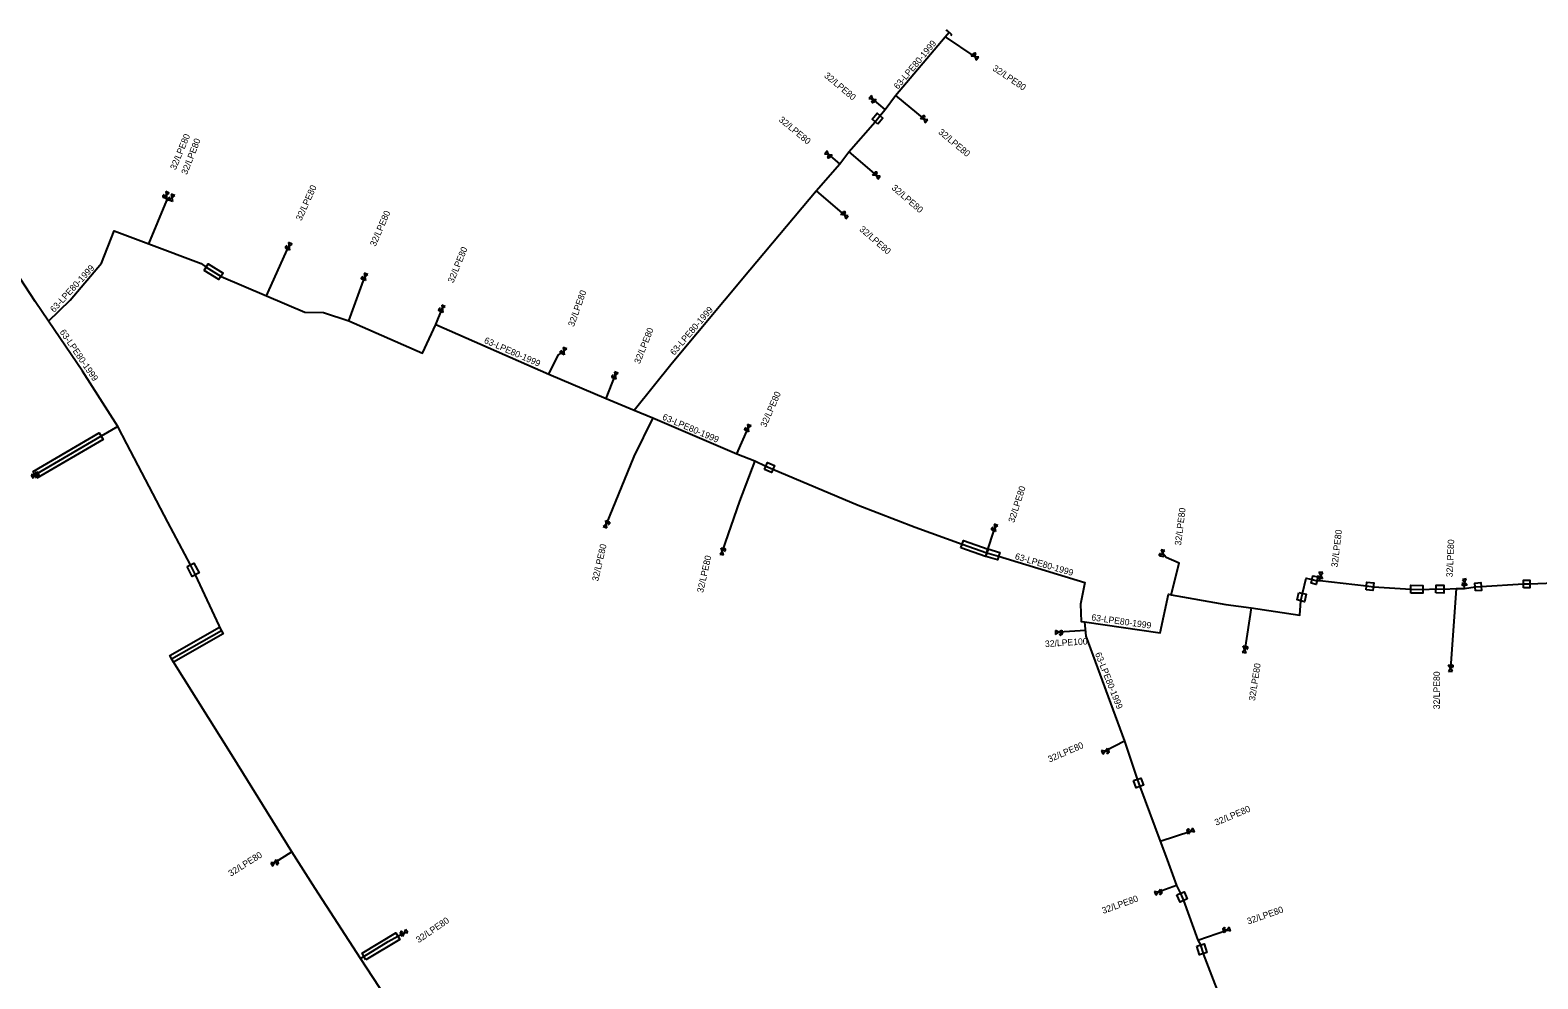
# Model space of a CAD drawing. Extents: x -762927 to -761200, y -1154354 to -1152015.
# Drawn here: x -761676.6 to -761442.6, y -1152408 to -1152260.8 of the extents above; entities that cross this region are included whole.
import ezdxf

# ---------------------------------------------------------------- set-up
doc = ezdxf.new("R2010")
doc.units = 0
for name, color, linetype in [('Vrstva 1', 7, 'Continuous'), ('Vrstva 21', 7, 'Continuous'), ('Vrstva 22', 7, 'Continuous'), ('Vrstva 29', 7, 'Continuous'), ('Vrstva 31', 7, 'Continuous'), ('Vrstva 32', 7, 'Continuous')]:
    doc.layers.add(name, color=color, linetype=linetype)

# ---------------------------------------------------------------- blocks, each defined once
blk = doc.blocks.new('DEC063-SN')
at = {"layer": 'Vrstva 1'}
for p, q in [((-0.5, -0.3), (0.5, 0.3)), ((0.5, -0.3), (-0.5, 0.3)), ((-0.5, 0.3), (-0.5, -0.3)), ((0.5, 0.3), (0.5, -0.3)), ((0.126, -0.318), (0.126, -0.458)), ((0.126, -0.384), (0.206, -0.384)), ((0.206, -0.458), (0.206, -0.318)), ((0.366, -0.458), (0.366, -0.318))]:
    blk.add_line(p, q, dxfattribs=at)
for points in [[(0.246, -0.318), (0.246, -0.418), (0.252, -0.438), (0.264, -0.451), (0.281, -0.458), (0.292, -0.458), (0.309, -0.451), (0.321, -0.438), (0.326, -0.418), (0.326, -0.318)], [(0.366, -0.318), (0.418, -0.318), (0.435, -0.325), (0.441, -0.331), (0.446, -0.344), (0.446, -0.364), (0.441, -0.378), (0.435, -0.384), (0.418, -0.391), (0.366, -0.391)]]:
    blk.add_lwpolyline(points, dxfattribs=at)
blk = doc.blocks.new('DEC130')
at = {"layer": 'Vrstva 1'}
blk.add_lwpolyline([(0.2, 0.5), (0, 0.5), (0, -0.5), (0.2, -0.5)], dxfattribs=at)

msp = doc.modelspace()

# ---------------------------------------------------------------- linework, layer by layer
at = {"layer": 'Vrstva 21'}
for points in [[(-761582.89, -1152319.81), (-761576.95, -1152312.47), (-761564.9, -1152298), (-761554.61, -1152285.76), (-761550.95, -1152281.56), (-761549.55, -1152279.71), (-761545.49, -1152275.05), (-761544.72, -1152274.11), (-761543.9, -1152273.16), (-761542.29, -1152270.99), (-761534.6, -1152261.85), (-761533.98, -1152261.17)], [(-761673.77, -1152305.98), (-761670.38, -1152302.71), (-761665.53, -1152296.98), (-761663.56, -1152291.99), (-761658.21, -1152293.99), (-761650.05, -1152297.02), (-761649.29, -1152297.62), (-761646.99, -1152299.04), (-761639.92, -1152302.07), (-761633.99, -1152304.61), (-761631.07, -1152304.65), (-761627.14, -1152305.92), (-761615.71, -1152310.97), (-761613.66, -1152306.5), (-761596.11, -1152314.22), (-761587.24, -1152318.01), (-761582.89, -1152319.81)], [(-761673.77, -1152305.98), (-761675.83, -1152302.94), (-761679.74, -1152297)], [(-761617.59, -1152416.73), (-761625.33, -1152404.89), (-761632.4, -1152394.03), (-761635.99, -1152388.35), (-761645.13, -1152373.62), (-761654.65, -1152358.4), (-761646.94, -1152353.98), (-761650.93, -1152345.33), (-761651.72, -1152343.79), (-761655.26, -1152337.2), (-761661.63, -1152325.02), (-761663.01, -1152322.34), (-761668.47, -1152313.73), (-761673.77, -1152305.98)], [(-761582.89, -1152319.81), (-761579.97, -1152321.01), (-761566.93, -1152326.59), (-761564.15, -1152327.67), (-761562.41, -1152328.48), (-761561.34, -1152328.94), (-761548.12, -1152334.52), (-761539.24, -1152337.93), (-761531.97, -1152340.58), (-761528.13, -1152341.92), (-761526.3, -1152342.45), (-761512.91, -1152346.54), (-761513.62, -1152349.91), (-761513.51, -1152352.59), (-761512.99, -1152352.67)], [(-761512.99, -1152352.67), (-761501.24, -1152354.37), (-761499.92, -1152348.35), (-761499.54, -1152348.44), (-761491.06, -1152349.98), (-761487.11, -1152350.48), (-761479.58, -1152351.6), (-761479.41, -1152349.39), (-761479.14, -1152348.23), (-761478.58, -1152345.89), (-761477.67, -1152346.08), (-761476.89, -1152346.26), (-761476.46, -1152346.24), (-761469.21, -1152347.08), (-761468.14, -1152347.2), (-761462.33, -1152347.58), (-761460.48, -1152347.61), (-761458.44, -1152347.54), (-761457.21, -1152347.58), (-761455.3, -1152347.46), (-761454.02, -1152347.46), (-761452.33, -1152347.23), (-761451.42, -1152347.16), (-761444.84, -1152346.77), (-761443.87, -1152346.77), (-761440.11, -1152346.61)], [(-761512.99, -1152352.67), (-761512.75, -1152354.87), (-761506.77, -1152371.17), (-761504.79, -1152377.08), (-761504.41, -1152378.2), (-761501.26, -1152386.66), (-761500.37, -1152389.03), (-761498.7, -1152393.56), (-761498.08, -1152394.78), (-761497.6, -1152395.89), (-761495.38, -1152402.02), (-761495, -1152402.77), (-761494.58, -1152404.14), (-761490.85, -1152413.85)]]:
    msp.add_lwpolyline(points, dxfattribs=at)
at = {"layer": 'Vrstva 29'}
for points in [[(-761545.03, -1152275.43), (-761545.95, -1152274.67), (-761545.18, -1152273.73), (-761544.26, -1152274.49)], [(-761649.6, -1152298.13), (-761648.97, -1152297.11), (-761646.67, -1152298.53), (-761647.31, -1152299.55)], [(-761675.56, -1152330.34), (-761676.16, -1152329.3), (-761665.89, -1152323.31), (-761665.29, -1152324.35)], [(-761562.65, -1152329.03), (-761562.17, -1152327.93), (-761561.1, -1152328.39), (-761561.58, -1152329.49)], [(-761532.17, -1152341.15), (-761531.77, -1152340.01), (-761527.93, -1152341.35), (-761528.33, -1152342.49)], [(-761652.25, -1152344.06), (-761651.19, -1152343.52), (-761650.4, -1152345.06), (-761651.46, -1152345.6)], [(-761528.3, -1152342.5), (-761527.96, -1152341.34), (-761526.13, -1152341.87), (-761526.47, -1152343.03)], [(-761477.8, -1152346.66), (-761477.54, -1152345.5), (-761476.76, -1152345.68), (-761477.02, -1152346.84)], [(-761479.72, -1152348.09), (-761478.56, -1152348.37), (-761478.83, -1152349.53), (-761479.99, -1152349.25)], [(-761469.28, -1152347.68), (-761469.14, -1152346.48), (-761468.07, -1152346.6), (-761468.21, -1152347.8)], [(-761462.34, -1152348.18), (-761462.32, -1152346.98), (-761460.47, -1152347.01), (-761460.49, -1152348.21)], [(-761458.46, -1152348.14), (-761458.42, -1152346.94), (-761457.19, -1152346.98), (-761457.23, -1152348.18)], [(-761452.28, -1152347.83), (-761452.38, -1152346.63), (-761451.47, -1152346.56), (-761451.37, -1152347.76)], [(-761444.84, -1152347.37), (-761444.84, -1152346.17), (-761443.87, -1152346.17), (-761443.87, -1152347.37)], [(-761654.35, -1152358.92), (-761654.95, -1152357.88), (-761647.24, -1152353.46), (-761646.64, -1152354.5)], [(-761505.36, -1152377.27), (-761504.22, -1152376.89), (-761503.84, -1152378.01), (-761504.98, -1152378.39)], [(-761498.63, -1152395.02), (-761497.53, -1152394.54), (-761497.05, -1152395.65), (-761498.15, -1152396.13)], [(-761624.49, -1152405.09), (-761625.11, -1152404.06), (-761619.85, -1152400.92), (-761619.23, -1152401.94)], [(-761495.57, -1152402.95), (-761494.43, -1152402.59), (-761494.01, -1152403.96), (-761495.15, -1152404.31)]]:
    msp.add_lwpolyline(points, close=True, dxfattribs=at)
at = {"layer": 'Vrstva 31'}
for points in [[(-761534.6, -1152261.85), (-761529.98, -1152264.96)], [(-761542.29, -1152270.99), (-761537.88, -1152274.67)], [(-761543.9, -1152273.16), (-761545.87, -1152271.51)], [(-761550.95, -1152281.56), (-761552.73, -1152280.09)], [(-761549.55, -1152279.71), (-761545.28, -1152283.4)], [(-761658.21, -1152293.99), (-761655.41, -1152287.24)], [(-761655.41, -1152287.23), (-761655.49, -1152286.45)], [(-761655.41, -1152287.24), (-761654.63, -1152286.85)], [(-761554.61, -1152285.76), (-761550.21, -1152289.55)], [(-761639.92, -1152302.07), (-761639.5, -1152301.15), (-761636.44, -1152294.37)], [(-761627.14, -1152305.92), (-761624.68, -1152299.13)], [(-761613.66, -1152306.5), (-761612.66, -1152304.06)], [(-761596.11, -1152314.22), (-761594.65, -1152311.27), (-761593.8, -1152310.63)], [(-761587.24, -1152318.01), (-761585.81, -1152314.41)], [(-761663.01, -1152322.34), (-761665.59, -1152323.83), (-761675.86, -1152329.82)], [(-761579.97, -1152321.01), (-761582.94, -1152327.01), (-761587.2, -1152337.48)], [(-761566.93, -1152326.59), (-761565.18, -1152322.59)], [(-761564.15, -1152327.67), (-761566.53, -1152333.91), (-761569.19, -1152341.7)], [(-761528.13, -1152341.92), (-761526.88, -1152338.05)], [(-761499.54, -1152348.44), (-761498.28, -1152343.52), (-761500.3, -1152342.68), (-761500.88, -1152342.01)], [(-761476.46, -1152346.24), (-761476.33, -1152345.45)], [(-761455.3, -1152347.46), (-761456.2, -1152359.84)], [(-761454.02, -1152347.46), (-761453.96, -1152346.51)], [(-761487.11, -1152350.48), (-761488.11, -1152356.93)], [(-761512.82, -1152354), (-761516.98, -1152354.26)], [(-761506.77, -1152371.17), (-761509.76, -1152372.72)], [(-761501.26, -1152386.66), (-761496.49, -1152385.13)], [(-761635.99, -1152388.35), (-761638.68, -1152390.04)], [(-761498.7, -1152393.56), (-761501.56, -1152394.59)], [(-761625.33, -1152404.89), (-761624.8, -1152404.58), (-761621.04, -1152402.25), (-761619.54, -1152401.43), (-761618.57, -1152400.92)], [(-761495.38, -1152402.02), (-761490.91, -1152400.47)]]:
    msp.add_lwpolyline(points, dxfattribs=at)

# ---------------------------------------------------------------- block references
at = {"layer": 'Vrstva 22', "rotation": -132.35745554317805}
msp.add_blockref('DEC130', (-761533.98, -1152261.17), dxfattribs=at)
at = {"layer": 'Vrstva 32'}
for p, rotation in [((-761529.98, -1152264.96), 140.3447028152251), ((-761545.87, -1152271.51), -39.94831105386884), ((-761537.88, -1152274.67), 140.62968055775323), ((-761552.73, -1152280.09), -39.55135005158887), ((-761545.28, -1152283.4), 142.14627501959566), ((-761655.49, -1152286.45), -112.76511667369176), ((-761654.63, -1152286.85), -111.41951384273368), ((-761550.21, -1152289.55), 139.70745554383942), ((-761636.44, -1152294.37), -112.97420826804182), ((-761624.68, -1152299.13), -110.43601401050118), ((-761612.66, -1152304.06), -113.78155284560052), ((-761593.8, -1152310.63), -112.51884170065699), ((-761585.81, -1152314.41), -110.11548336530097), ((-761565.18, -1152322.59), -113.51558053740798), ((-761675.86, -1152329.82), 30.252966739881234), ((-761587.2, -1152337.48), 67.85973327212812), ((-761526.88, -1152338.05), -109.64012499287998), ((-761569.19, -1152341.7), 78.4803055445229), ((-761500.88, -1152342.01), -101.50610832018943), ((-761476.33, -1152345.45), -93.93391666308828), ((-761453.96, -1152346.51), -82.92992497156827), ((-761516.98, -1152354.26), 3.5763344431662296), ((-761488.11, -1152356.93), 81.18709723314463), ((-761456.2, -1152359.84), 92.84639436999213), ((-761509.76, -1152372.72), 21.430008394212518), ((-761496.49, -1152385.13), -157.64059720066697), ((-761638.68, -1152390.04), 32.1392082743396), ((-761501.56, -1152394.59), 19.805969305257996), ((-761618.57, -1152400.92), -144.47032782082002), ((-761490.91, -1152400.47), -160.32060567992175)]:
    msp.add_blockref('DEC063-SN', p, dxfattribs=dict(at, rotation=rotation))

# ---------------------------------------------------------------- texts
at = {"layer": 'Vrstva 21'}
for rotation, p in [(49.924, (-761541.93, -1152270.09)), (47.431, (-761672.89, -1152304.71)), (49.414, (-761576.64, -1152311.37)), (304.367, (-761672.08, -1152307.68)), (336.256, (-761606.26, -1152309.32)), (336.894, (-761578.6, -1152321.22)), (343.536, (-761523.86, -1152342.89)), (351.998, (-761511.96, -1152352.41)), (291.723, (-761511.37, -1152357.59))]:
    msp.add_text('63-LPE80-1999', height=1, rotation=rotation, dxfattribs=at).set_placement(p)
at = {"layer": 'Vrstva 31'}
for s, rotation, p in [('32/LPE80', 326.053, (-761527.35, -1152266.98)), ('32/LPE80', 320.052, (-761553.47, -1152268.03)), ('32/LPE80', 320.449, (-761560.51, -1152274.89)), ('32/LPE80', 67.322, (-761654.02, -1152282.6)), ('32/LPE80', 68.627, (-761652.27, -1152283.33)), ('32/LPE80', 320.156, (-761535.75, -1152276.8)), ('32/LPE80', 65.709, (-761634.53, -1152290.5)), ('32/LPE80', 319.167, (-761543, -1152285.44)), ('32/LPE80', 66.488, (-761623.02, -1152294.49)), ('32/LPE80', 319.26, (-761548, -1152291.87)), ('32/LPE80', 67.714, (-761610.93, -1152300.15)), ('32/LPE80', 70.415, (-761592.23, -1152306.93)), ('32/LPE80', 68.336, (-761581.99, -1152312.7)), ('32/LPE80', 66.371, (-761562.42, -1152322.56)), ('32/LPE80', 72.1, (-761523.9, -1152337.35)), ('32/LPE80', 82.924, (-761498, -1152340.84)), ('32/LPE80', 83.2, (-761473.71, -1152344.23)), ('32/LPE80', 77.048, (-761588.46, -1152346.42)), ('32/LPE80', 87.473, (-761455.85, -1152345.74)), ('32/LPE80', 77.265, (-761572.17, -1152348.2)), ('32/LPE100', 3.576, (-761519.08, -1152356.56)), ('32/LPE80', 81.187, (-761486.52, -1152364.95)), ('32/LPE80', 89.876, (-761457.83, -1152366.21)), ('32/LPE80', 23.433, (-761518.41, -1152374.49)), ('32/LPE80', 22.784, (-761492.54, -1152384.3)), ('32/LPE80', 32.139, (-761645.47, -1152392.2)), ('32/LPE80', 19.806, (-761510.07, -1152397.97)), ('32/LPE80', 19.124, (-761487.57, -1152399.62)), ('32/LPE80', 34.364, (-761616.32, -1152402.53))]:
    msp.add_text(s, height=1, rotation=rotation, dxfattribs=at).set_placement(p)

doc.saveas('drawing.dxf')
